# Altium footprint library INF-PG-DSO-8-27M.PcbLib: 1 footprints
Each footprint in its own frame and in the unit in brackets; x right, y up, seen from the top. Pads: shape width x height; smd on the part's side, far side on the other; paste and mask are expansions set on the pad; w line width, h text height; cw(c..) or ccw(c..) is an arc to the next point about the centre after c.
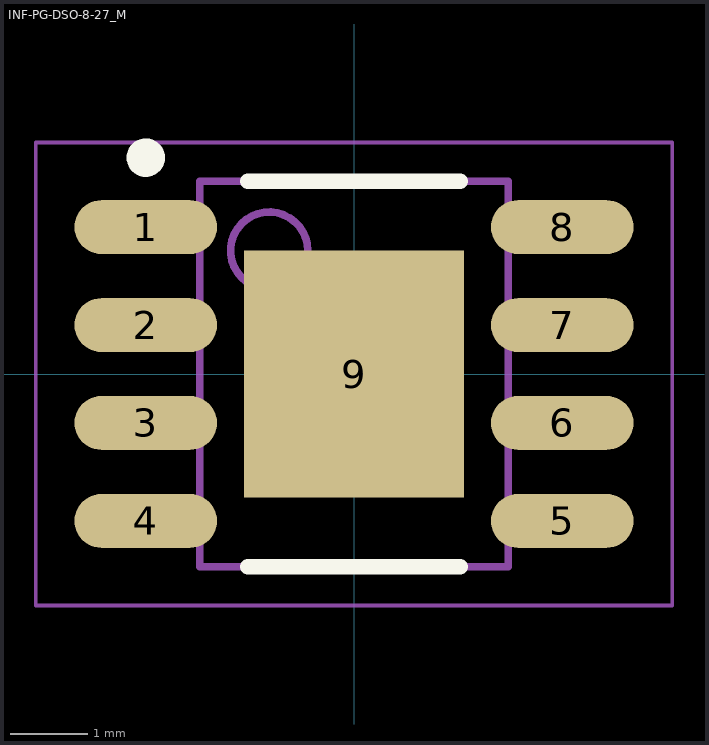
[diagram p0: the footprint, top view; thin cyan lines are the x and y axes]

## INF-PG-DSO-8-27_M [mm] "SOP, 8-Leads, Body 4.9x3.9mm, Pitch 1.27mm, Thermal Pad 3.2x2.85mm, IPC Low Density"
height 1.7
pads (9):
  oval 1.85x0.7 smd: 1(-2.7,1.905) 2(-2.7,0.635) 3(-2.7,-0.635) 4(-2.7,-1.905) 5(2.7,-1.905) 6(2.7,-0.635) 7(2.7,0.635) 8(2.7,1.905)
  rect 2.85x3.2 smd: 9(0,0)
Top Overlay:
  circle w0.25: c-2.7,2.805 r0.125
  lines w0.2: -1.375,-2.5 1.375,-2.5 ; -1.375,2.5 1.375,2.5
Mechanical 13:
  circle w0.1: c-1.1,1.6 r0.5
  lines w0.1: -2,-2.5 -2,2.5 2,2.5 2,-2.5 -2,-2.5
Mechanical 15:
  lines w0.05: -4.125,-3 -4.125,3 4.125,3 4.125,-3 -4.125,-3
  lines w0.1: -0.5,0 0.5,0 ; 0,-0.5 0,0.5
3D body: height 1.7, standoff 0, extent -2,-2.5 2,2.5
